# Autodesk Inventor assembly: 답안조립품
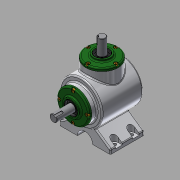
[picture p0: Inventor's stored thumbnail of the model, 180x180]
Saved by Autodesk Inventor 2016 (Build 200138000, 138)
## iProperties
Created: 2017-04
Part Number: 답안조립품
Material: 일반
Document SubType Name: Assembly
Designer: CAMTIC
Author: CAMTIC
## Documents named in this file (14)
- C:\Users\CAMTIC\Desktop\470407V1028\답안조립품.iam
- C:\Users\CAMTIC\Desktop\470407V1028\본체.ipt
- C:\Users\CAMTIC\Desktop\470407V1028\메인 베벨기어.ipt
- C:\Users\CAMTIC\Desktop\470407V1028\메인 축.ipt
- 메인 축.ipt
- C:\Users\CAMTIC\Desktop\470407V1028\베어링 6203.ipt
- C:\Users\CAMTIC\Desktop\470407V1028\볼트 M4.ipt
- C:\Users\CAMTIC\Desktop\470407V1028\서브 베벨기어.ipt
- C:\Users\CAMTIC\Desktop\470407V1028\서브 축.ipt
- 서브 축.ipt
- C:\Users\CAMTIC\Desktop\470407V1028\오일실 17 32 8.ipt
- C:\Users\CAMTIC\Desktop\470407V1028\커버.ipt
- C:\Users\CAMTIC\Desktop\470407V1028\키 4x4.ipt
- C:\Users\CAMTIC\Desktop\470407V1028\키 5x5.ipt
